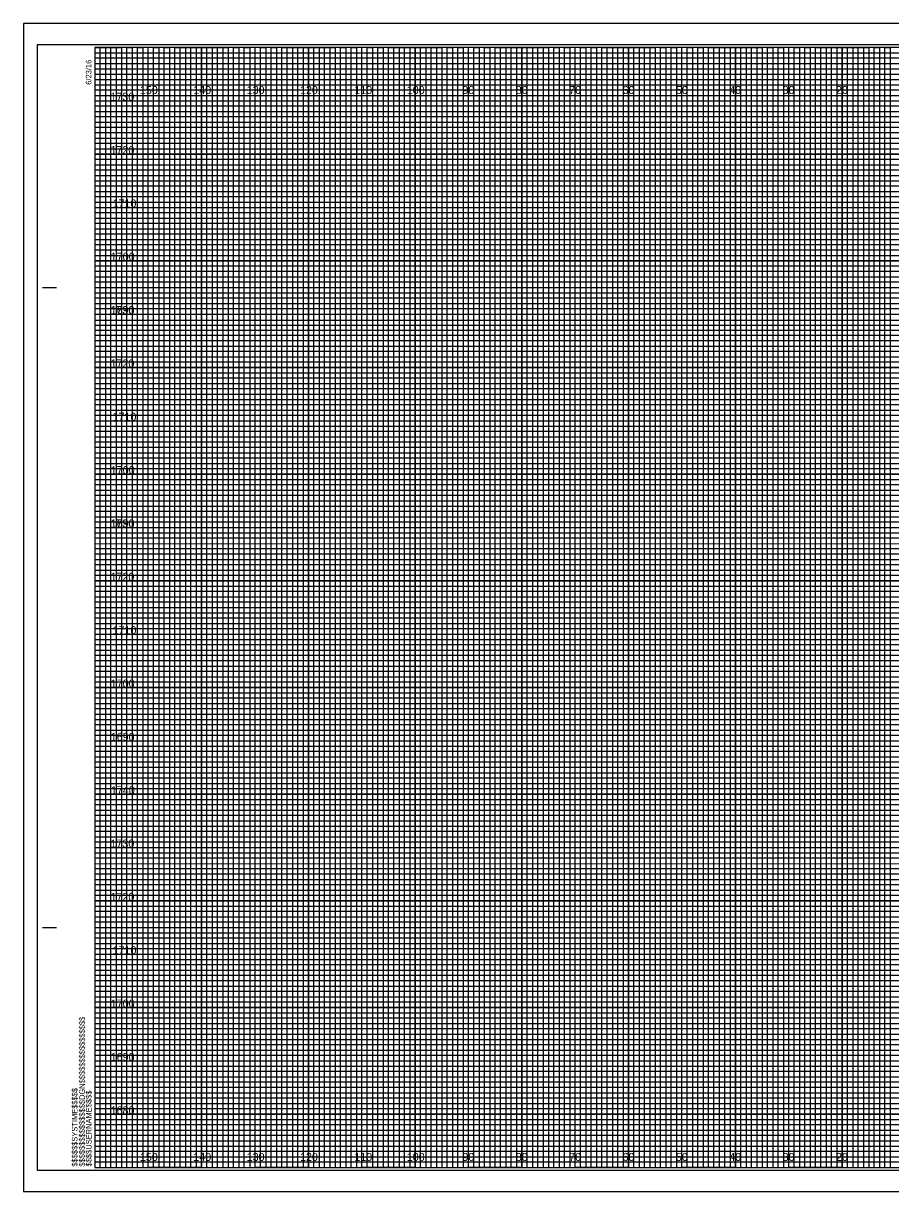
# Model space of a CAD drawing. Extents: x -15 to 323, y -5 to 6170.
# Drawn here: x -13.4 to 149.1, y 215.5 to 434.5 of the extents above; entities that cross this region are included whole.
import ezdxf

# ---------------------------------------------------------------- set-up
doc = ezdxf.new("R2010")
doc.units = 0
for name, color, linetype in [('Prop XS DDE', 7, 'Continuous'), ('Prop XS DDE Slope Text', 7, 'Continuous'), ('Prop XS DDE Text', 7, 'Continuous'), ('Prop XS Earthwork Shape', 7, 'Continuous'), ('Prop XS Noise Wall', 7, 'Continuous'), ('Prop XS Retaining Wall', 7, 'Continuous'), ('Prop XS Station Labels', 7, 'Continuous'), ('Scratch_Level_3', 7, 'Continuous'), ('Scratch_Level_7', 7, 'Continuous'), ('Scratch_Level_8', 7, 'Continuous'), ('Sheet Cross Section Grid Minor 1 CELL', 7, 'Continuous')]:
    doc.layers.add(name, color=color, linetype=linetype)

msp = doc.modelspace()

# ---------------------------------------------------------------- linework, layer by layer
at = {"layer": 'Prop XS DDE'}
msp.add_lwpolyline([(-13.4, 215.5), (323.3, 215.5), (323.3, 434.5), (-13.4, 434.5)], close=True, dxfattribs=at)
at = {"layer": 'Prop XS DDE Slope Text'}
msp.add_lwpolyline([(-10.8, 219.5), (322.4, 219.5), (322.4, 430.5), (-10.8, 430.5)], close=True, dxfattribs=at)
at = {"layer": 'Prop XS DDE Text'}
for p, q in [((10, 220), (10, 430)), ((20, 220), (20, 430)), ((30, 220), (30, 430)), ((40, 220), (40, 430)), ((50, 220), (50, 430)), ((60, 220), (60, 430)), ((70, 220), (70, 430)), ((80, 220), (80, 430)), ((90, 220), (90, 430)), ((100, 220), (100, 430)), ((110, 220), (110, 430)), ((120, 220), (120, 430)), ((130, 220), (130, 430)), ((140, 220), (140, 430)), ((0, 420), (320, 420)), ((0, 410), (320, 410)), ((0, 400), (320, 400)), ((0, 390), (320, 390)), ((0, 380), (320, 380)), ((0, 370), (320, 370)), ((0, 360), (320, 360)), ((0, 350), (320, 350)), ((0, 340), (320, 340)), ((0, 330), (320, 330)), ((0, 320), (320, 320)), ((0, 310), (320, 310)), ((0, 300), (320, 300)), ((0, 290), (320, 290)), ((0, 280), (320, 280)), ((0, 270), (320, 270)), ((0, 260), (320, 260)), ((0, 250), (320, 250)), ((0, 240), (320, 240)), ((0, 230), (320, 230))]:
    msp.add_line(p, q, dxfattribs=at)
at = {"layer": 'Prop XS Earthwork Shape'}
for p, q in [((10, 430), (0, 430)), ((10, 220), (10, 430)), ((30, 430), (20, 430)), ((20, 430), (20, 220)), ((30, 220), (30, 430)), ((50, 430), (40, 430)), ((40, 430), (40, 220)), ((50, 220), (50, 430)), ((70, 430), (60, 430)), ((60, 430), (60, 220)), ((70, 220), (70, 430)), ((90, 430), (80, 430)), ((80, 430), (80, 220)), ((90, 220), (90, 430)), ((110, 430), (100, 430)), ((100, 430), (100, 220)), ((110, 220), (110, 430)), ((130, 430), (120, 430)), ((120, 430), (120, 220)), ((130, 220), (130, 430)), ((150, 430), (140, 430)), ((140, 430), (140, 220)), ((20, 220), (10, 220)), ((40, 220), (30, 220)), ((60, 220), (50, 220)), ((80, 220), (70, 220)), ((100, 220), (90, 220)), ((120, 220), (110, 220)), ((140, 220), (130, 220))]:
    msp.add_line(p, q, dxfattribs=at)
for points in [[(0, 420), (320, 420), (320, 410), (0, 410)], [(0, 400), (320, 400), (320, 390), (0, 390)], [(0, 380), (320, 380), (320, 370), (0, 370)], [(0, 360), (320, 360), (320, 350), (0, 350)], [(0, 340), (320, 340), (320, 330), (0, 330)], [(0, 320), (320, 320), (320, 310), (0, 310)], [(0, 300), (320, 300), (320, 290), (0, 290)], [(0, 280), (320, 280), (320, 270), (0, 270)], [(0, 260), (320, 260), (320, 250), (0, 250)], [(0, 240), (320, 240), (320, 230), (0, 230)]]:
    msp.add_lwpolyline(points, dxfattribs=at)
at = {"layer": 'Prop XS Noise Wall'}
for p, q in [((-9.8, 385), (-7.3, 385)), ((-9.7, 385), (-7.2, 385)), ((-9.8, 265), (-7.3, 265)), ((-9.7, 265), (-7.2, 265)), ((0, 220), (0, 220)), ((0, 220), (0, 220)), ((0, 220), (0, 220)), ((0, 220), (0, 220)), ((0, 220), (0, 220)), ((0, 220), (0, 220)), ((0, 220), (0, 220))]:
    msp.add_line(p, q, dxfattribs=at)
msp.add_lwpolyline([(320, 430), (0, 430), (0, 220), (320, 220)], close=True, dxfattribs=at)
at = {"layer": 'Prop XS Retaining Wall'}
for points in [[(0, 220), (1, 220), (1, 430), (2, 430), (2, 220)], [(2, 220), (3, 220), (3, 430), (4, 430), (4, 220)], [(5, 220), (6, 220), (6, 430), (7, 430), (7, 220)], [(7, 220), (8, 220), (8, 430), (9, 430), (9, 220)], [(10, 220), (11, 220), (11, 430), (12, 430), (12, 220)], [(12, 220), (13, 220), (13, 430), (14, 430), (14, 220)], [(15, 220), (16, 220), (16, 430), (17, 430), (17, 220)], [(17, 220), (18, 220), (18, 430), (19, 430), (19, 220)], [(20, 220), (21, 220), (21, 430), (22, 430), (22, 220)], [(22, 220), (23, 220), (23, 430), (24, 430), (24, 220)], [(25, 220), (26, 220), (26, 430), (27, 430), (27, 220)], [(27, 220), (28, 220), (28, 430), (29, 430), (29, 220)], [(30, 220), (31, 220), (31, 430), (32, 430), (32, 220)], [(32, 220), (33, 220), (33, 430), (34, 430), (34, 220)], [(35, 220), (36, 220), (36, 430), (37, 430), (37, 220)], [(37, 220), (38, 220), (38, 430), (39, 430), (39, 220)], [(40, 220), (41, 220), (41, 430), (42, 430), (42, 220)], [(42, 220), (43, 220), (43, 430), (44, 430), (44, 220)], [(45, 220), (46, 220), (46, 430), (47, 430), (47, 220)], [(47, 220), (48, 220), (48, 430), (49, 430), (49, 220)], [(50, 220), (51, 220), (51, 430), (52, 430), (52, 220)], [(52, 220), (53, 220), (53, 430), (54, 430), (54, 220)], [(55, 220), (56, 220), (56, 430), (57, 430), (57, 220)], [(57, 220), (58, 220), (58, 430), (59, 430), (59, 220)], [(60, 220), (61, 220), (61, 430), (62, 430), (62, 220)], [(62, 220), (63, 220), (63, 430), (64, 430), (64, 220)], [(65, 220), (66, 220), (66, 430), (67, 430), (67, 220)], [(67, 220), (68, 220), (68, 430), (69, 430), (69, 220)], [(70, 220), (71, 220), (71, 430), (72, 430), (72, 220)], [(72, 220), (73, 220), (73, 430), (74, 430), (74, 220)], [(75, 220), (76, 220), (76, 430), (77, 430), (77, 220)], [(77, 220), (78, 220), (78, 430), (79, 430), (79, 220)], [(80, 220), (81, 220), (81, 430), (82, 430), (82, 220)], [(82, 220), (83, 220), (83, 430), (84, 430), (84, 220)], [(85, 220), (86, 220), (86, 430), (87, 430), (87, 220)], [(87, 220), (88, 220), (88, 430), (89, 430), (89, 220)], [(90, 220), (91, 220), (91, 430), (92, 430), (92, 220)], [(92, 220), (93, 220), (93, 430), (94, 430), (94, 220)], [(95, 220), (96, 220), (96, 430), (97, 430), (97, 220)], [(97, 220), (98, 220), (98, 430), (99, 430), (99, 220)], [(100, 220), (101, 220), (101, 430), (102, 430), (102, 220)], [(102, 220), (103, 220), (103, 430), (104, 430), (104, 220)], [(105, 220), (106, 220), (106, 430), (107, 430), (107, 220)], [(107, 220), (108, 220), (108, 430), (109, 430), (109, 220)], [(110, 220), (111, 220), (111, 430), (112, 430), (112, 220)], [(112, 220), (113, 220), (113, 430), (114, 430), (114, 220)], [(115, 220), (116, 220), (116, 430), (117, 430), (117, 220)], [(117, 220), (118, 220), (118, 430), (119, 430), (119, 220)], [(120, 220), (121, 220), (121, 430), (122, 430), (122, 220)], [(122, 220), (123, 220), (123, 430), (124, 430), (124, 220)], [(125, 220), (126, 220), (126, 430), (127, 430), (127, 220)], [(127, 220), (128, 220), (128, 430), (129, 430), (129, 220)], [(130, 220), (131, 220), (131, 430), (132, 430), (132, 220)], [(132, 220), (133, 220), (133, 430), (134, 430), (134, 220)], [(135, 220), (136, 220), (136, 430), (137, 430), (137, 220)], [(137, 220), (138, 220), (138, 430), (139, 430), (139, 220)], [(140, 220), (141, 220), (141, 430), (142, 430), (142, 220)], [(142, 220), (143, 220), (143, 430), (144, 430), (144, 220)], [(145, 220), (146, 220), (146, 430), (147, 430), (147, 220)], [(147, 220), (148, 220), (148, 430), (149, 430), (149, 220)]]:
    msp.add_lwpolyline(points, dxfattribs=at)
at = {"layer": 'Prop XS Station Labels'}
for points in [[(0, 430), (5, 430), (5, 220), (15, 220), (15, 430), (25, 430), (25, 220), (35, 220), (35, 430), (45, 430), (45, 220), (55, 220), (55, 430), (65, 430), (65, 220), (75, 220), (75, 430), (85, 430), (85, 220), (95, 220), (95, 430), (105, 430), (105, 220), (115, 220), (115, 430), (125, 430), (125, 220), (135, 220), (135, 430), (145, 430), (145, 220), (155, 220)], [(0, 425), (275, 425)], [(0, 405), (320, 405), (320, 415), (0, 415)], [(0, 385), (320, 385), (320, 395), (0, 395)], [(0, 365), (320, 365), (320, 375), (0, 375)], [(0, 345), (320, 345), (320, 355), (0, 355)], [(0, 325), (320, 325), (320, 335), (0, 335)], [(0, 305), (320, 305), (320, 315), (0, 315)], [(0, 285), (320, 285), (320, 295), (0, 295)], [(0, 265), (320, 265), (320, 275), (0, 275)], [(0, 245), (320, 245), (320, 255), (0, 255)], [(0, 225), (320, 225), (320, 235), (0, 235)]]:
    msp.add_lwpolyline(points, dxfattribs=at)
at = {"layer": 'Scratch_Level_7'}
for p, q in [((323.3, 434.5), (-13.4, 434.5)), ((-13.4, 434.5), (-13.4, 215.5)), ((-13.4, 215.5), (323.3, 215.5))]:
    msp.add_line(p, q, dxfattribs=at)
at = {"layer": 'Sheet Cross Section Grid Minor 1 CELL'}
for p, q in [((0, 429), (260, 429)), ((260, 427.98), (0, 427.98)), ((0, 427.98), (0, 427)), ((0, 427), (260, 427)), ((260, 425.89), (0, 425.89)), ((0, 425.89), (0, 424)), ((0, 424), (320, 424))]:
    msp.add_line(p, q, dxfattribs=at)
for points in [[(0, 423), (270, 423), (320, 423), (320, 422), (0, 422)], [(0, 421), (320, 421), (320, 419), (0, 419)], [(0, 418), (320, 418), (320, 417), (0, 416.98)], [(0, 416), (320, 416), (320, 414), (0, 414)], [(0, 413), (320, 413), (320, 412), (0, 412)], [(0, 411), (320, 411), (320, 409), (0, 409)], [(0, 408), (320, 408), (320, 407), (0, 407)], [(0, 406), (320, 406), (320, 404), (0, 404)], [(0, 403), (320, 403), (320, 402), (0, 402)], [(0, 401), (320, 401), (320, 399), (0, 399)], [(0, 398), (320, 398), (320, 397), (0, 397)], [(0, 396), (320, 396), (320, 393.95), (320, 393), (320, 392), (0, 392)], [(0, 394), (320, 394), (320, 393), (0, 393)], [(0, 391), (320, 391), (320, 389), (0, 389.03)], [(0, 389.03), (320, 389), (320, 388), (0, 388)], [(0, 387), (320, 387), (320, 386), (0, 386)], [(0, 384), (320, 384), (320, 383), (0, 383)], [(0, 382), (320, 382), (320, 381), (0, 381)], [(-0.07, 378.89), (320, 378.89), (320, 377.88), (-0.07, 377.88)], [(0, 377), (320, 377), (320, 376), (0, 376)], [(0, 374), (320, 374), (320, 373), (0, 373)], [(0, 372), (320, 372), (320, 371), (0, 371)], [(0, 369), (320, 369), (320, 368), (0, 368)], [(0, 367), (320, 367), (320, 366), (0, 366)], [(0, 364), (320, 364), (320, 363), (0, 363)], [(0, 362), (320, 362), (320, 361), (0, 361)], [(0, 359), (320, 359), (319.99, 357.98), (0, 358)], [(0, 357), (320, 357), (320, 356), (0, 356)], [(0, 354), (320, 354), (320, 353), (0, 353)], [(0, 352), (320, 352), (320, 351), (0, 351)], [(0, 349), (320, 349), (320, 348), (0, 348)], [(0, 347), (320, 347), (320, 346), (0, 346)], [(0, 344), (320, 344), (320, 343), (0, 343)], [(0, 342), (320, 342), (320, 341), (0, 341)], [(0, 339), (320, 339), (320, 338), (0, 338)], [(0, 336.99), (320.07, 336.91), (320, 336), (0, 336)], [(0, 334), (320, 334), (320, 333), (0, 333)], [(0, 332), (320, 332), (320, 331), (0, 331)], [(0, 329), (320, 329), (320, 328), (0, 328)], [(0, 327), (320, 327), (320, 326), (0, 326)], [(0, 324), (320, 324), (320, 323), (0, 323)], [(0, 322), (320, 322), (320, 321), (0, 321)], [(0, 319), (320, 319), (320, 318), (0, 318)], [(0, 317), (320, 317), (320, 316), (0, 316)], [(0, 314), (320, 314), (320, 313), (0, 313)], [(0, 312), (320, 312), (320, 311), (0, 311)], [(0, 309), (320, 309), (320, 308), (0, 308)], [(0, 307), (320, 307), (320, 306), (0, 306)], [(0, 304), (320, 304), (320, 303), (0, 303)], [(0, 302), (320, 302), (320, 301), (0, 301)], [(0, 299), (320, 299), (319.99, 297.98), (0, 298)], [(0, 297), (320, 297), (320, 296), (0, 296)], [(0, 294), (320, 294), (320, 293), (0, 293)], [(0, 292), (320, 292), (320, 291), (0, 291)], [(0, 289), (320, 289), (320, 288), (0, 288)], [(0, 287), (320, 287), (320, 286), (0, 286)], [(0, 284), (320, 284), (320, 283), (0, 283)], [(0, 282), (320, 282), (320, 281), (0, 281)], [(0, 279), (320, 279), (320, 278), (0, 278)], [(0, 276.99), (320.07, 276.91), (320, 276), (0, 276)], [(0, 274), (320, 274), (320, 273), (0, 273)], [(0, 272), (320, 272), (320, 271), (0, 271)], [(0, 269), (320, 269), (320, 268), (0, 268)], [(0, 267), (320, 267), (320, 266), (0, 266)], [(0, 264), (320, 264), (320, 263), (0, 263)], [(0, 262), (320, 262), (320, 261), (0, 261)], [(0, 259), (320, 259), (320, 258), (0, 258)], [(0, 257), (320, 257), (320, 256), (0, 256)], [(0, 254), (320, 254), (320, 253), (0, 253)], [(0, 252), (320, 252), (320, 251), (0, 251)], [(0, 249), (320, 249), (320, 248), (0, 248)], [(0, 247), (320, 247), (320, 246), (0, 246)], [(0, 244), (320, 244), (320, 243), (0, 243)], [(0, 242), (320, 242), (320, 241), (0, 241)], [(0, 239), (320, 239), (320, 238), (0, 238)], [(0, 237), (320, 237), (320, 236), (0, 236)], [(0, 234), (320, 234), (320, 233), (0, 233)], [(0, 232), (320, 232), (320, 231), (0, 231)], [(0, 229), (320, 229), (320, 228), (0, 228)], [(0, 227), (320, 227), (320, 226), (0, 226)], [(0, 224), (320, 224), (320, 223), (0, 223)], [(0, 222), (320, 222), (320, 221), (0, 221)]]:
    msp.add_lwpolyline(points, dxfattribs=at)

# ---------------------------------------------------------------- texts
at = {"layer": 'Prop XS Noise Wall'}
for s, p in [('6/23/16', (-0.65, 423)), ('$$$$$$$$$$$$$$$$DGN$$$$$$$$$$$$$$$$', (-1.88, 220.18)), ('$$$$$$SYSTIME$$$$$', (-3.26, 220.18)), ('$$$$USERNAME$$$$', (-0.62, 220.23))]:
    msp.add_text(s, height=1.05, rotation=90, dxfattribs=at).set_placement(p)
at = {"layer": 'Scratch_Level_3'}
for s, p in [('1730', (2.92, 420)), ('1720', (2.93, 410)), ('1710', (3.31, 400)), ('1700', (2.98, 390)), ('1730', (2.92, 380)), ('1690', (2.97, 380)), ('1720', (2.93, 370)), ('1710', (3.31, 360)), ('1700', (2.98, 350)), ('1730', (2.92, 340)), ('1690', (2.97, 340)), ('1720', (2.93, 330)), ('1710', (3.31, 320)), ('1700', (2.98, 310)), ('1690', (2.97, 300)), ('1740', (3, 290)), ('1730', (2.92, 280)), ('1720', (2.93, 270)), ('1710', (3.31, 260)), ('1700', (2.98, 250)), ('1690', (2.97, 240)), ('1680', (2.95, 230))]:
    msp.add_text(s, height=1.5, dxfattribs=at).set_placement(p)
at = {"layer": 'Scratch_Level_8'}
for s, p in [('150', (8.44, 421.25)), ('140', (18.44, 421.25)), ('130', (28.44, 421.25)), ('120', (38.44, 421.25)), ('110', (48.62, 421.25)), ('100', (58.44, 421.25)), ('90', (68.86, 421.25)), ('80', (78.86, 421.25)), ('70', (88.86, 421.25)), ('60', (98.86, 421.25)), ('50', (108.86, 421.25)), ('40', (118.86, 421.25)), ('30', (128.86, 421.25)), ('20', (138.86, 421.25)), ('150', (8.44, 221.25)), ('140', (18.44, 221.25)), ('130', (28.44, 221.25)), ('120', (38.44, 221.25)), ('110', (48.62, 221.25)), ('100', (58.44, 221.25)), ('90', (68.86, 221.25)), ('80', (78.86, 221.25)), ('70', (88.86, 221.25)), ('60', (98.86, 221.25)), ('50', (108.86, 221.25)), ('40', (118.86, 221.25)), ('30', (128.86, 221.25)), ('20', (138.86, 221.25))]:
    msp.add_text(s, height=1.5, dxfattribs=at).set_placement(p)

doc.saveas('drawing.dxf')
